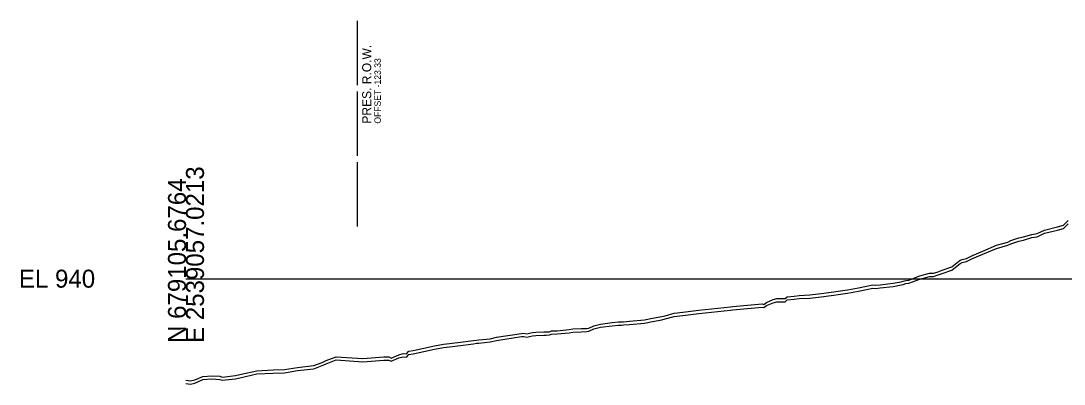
# Model space of a CAD drawing. Extents: x -26 to 2539581, y -16 to 679563.
# Drawn here: x -25.7 to 136.6, y 5483.6 to 5540.1 of the extents above; entities that cross this region are included whole.
import ezdxf

# ---------------------------------------------------------------- set-up
doc = ezdxf.new("R2010")
doc.units = 0
for name, color, linetype in [('DESIGN - SHEET - Light Grid', 7, 'Continuous'), ('SURVEY - GROUND - Bottom of Topsoil Layer', 7, 'Continuous'), ('SURVEY - GROUND - Top of Ground', 7, 'Continuous'), ('SURVEY - PROPERTY - ROW Lines', 7, 'Continuous'), ('SURVEY - PROPERTY - ROW Lines Text', 7, 'Continuous')]:
    doc.layers.add(name, color=color, linetype=linetype)

msp = doc.modelspace()

# ---------------------------------------------------------------- linework, layer by layer
at = {"layer": 'DESIGN - SHEET - Light Grid'}
msp.add_line((0, 5500), (150, 5500), dxfattribs=at)
at = {"layer": 'SURVEY - GROUND - Bottom of Topsoil Layer'}
for p, q in [((136.53, 5507.81), (137.28, 5508.56)), ((131.63, 5506.4), (132.46, 5506.51)), ((132.46, 5506.51), (133.57, 5507.08)), ((133.57, 5507.08), (135.6, 5507.58)), ((135.6, 5507.58), (136.53, 5507.81)), ((126.12, 5504.71), (127.88, 5505.2)), ((127.88, 5505.2), (128.34, 5505.44)), ((128.34, 5505.44), (128.99, 5505.66)), ((128.99, 5505.66), (129.62, 5505.86)), ((129.62, 5505.86), (130.32, 5506.02)), ((130.32, 5506.02), (131.63, 5506.4)), ((122.39, 5503.12), (123.97, 5503.81)), ((123.97, 5503.81), (126.12, 5504.71)), ((119.16, 5501.35), (120.49, 5502.36)), ((120.49, 5502.36), (120.8, 5502.51)), ((120.8, 5502.51), (121.45, 5502.65)), ((121.45, 5502.65), (122.39, 5503.12)), ((114.17, 5499.94), (115.72, 5500.36)), ((115.72, 5500.36), (116.33, 5500.36)), ((116.33, 5500.36), (116.87, 5500.53)), ((116.87, 5500.53), (117.66, 5500.82)), ((117.66, 5500.82), (119.16, 5501.35)), ((105.91, 5498.33), (106.89, 5498.52)), ((106.89, 5498.52), (107.32, 5498.48)), ((107.32, 5498.48), (108, 5498.55)), ((108, 5498.55), (110.05, 5498.8)), ((110.05, 5498.8), (111.29, 5499.03)), ((111.29, 5499.03), (111.6, 5499.1)), ((111.6, 5499.1), (112, 5499.24)), ((112, 5499.24), (112.46, 5499.28)), ((112.46, 5499.28), (114.17, 5499.94)), ((93.55, 5496.69), (94.62, 5496.79)), ((94.62, 5496.79), (95.4, 5496.89)), ((95.4, 5496.89), (97.07, 5496.98)), ((97.07, 5496.98), (99.26, 5497.23)), ((99.26, 5497.23), (99.99, 5497.33)), ((99.99, 5497.33), (100.79, 5497.45)), ((100.79, 5497.45), (101.47, 5497.54)), ((101.47, 5497.54), (102.92, 5497.76)), ((102.92, 5497.76), (104.63, 5498.08)), ((104.63, 5498.08), (105.91, 5498.33)), ((84.74, 5495.1), (85.1, 5495.16)), ((85.1, 5495.16), (89.65, 5495.58)), ((89.65, 5495.58), (89.94, 5495.5)), ((89.94, 5495.5), (90.33, 5495.81)), ((90.33, 5495.81), (91.38, 5496.24)), ((91.38, 5496.24), (91.92, 5496.4)), ((91.92, 5496.4), (93.22, 5496.4)), ((93.22, 5496.4), (93.55, 5496.69)), ((72.58, 5493.35), (74.03, 5493.61)), ((74.03, 5493.61), (74.54, 5493.73)), ((74.54, 5493.73), (75.97, 5494.11)), ((75.97, 5494.11), (77.3, 5494.27)), ((77.3, 5494.27), (79.79, 5494.6)), ((79.79, 5494.6), (84.74, 5495.1)), ((62.71, 5491.82), (63.48, 5492.17)), ((63.48, 5492.17), (64.52, 5492.43)), ((64.52, 5492.43), (66.34, 5492.66)), ((66.34, 5492.66), (67.31, 5492.76)), ((67.31, 5492.76), (67.75, 5492.76)), ((67.75, 5492.76), (68.07, 5492.8)), ((68.07, 5492.8), (68.99, 5492.87)), ((68.99, 5492.87), (71.34, 5493.08)), ((71.34, 5493.08), (72.58, 5493.35)), ((47.35, 5490.16), (48.34, 5490.38)), ((48.34, 5490.38), (52.21, 5490.98)), ((52.21, 5490.98), (52.55, 5491)), ((52.55, 5491), (53.02, 5490.92)), ((53.02, 5490.92), (53.45, 5491)), ((53.45, 5491), (53.93, 5491.12)), ((53.93, 5491.12), (54.43, 5491.16)), ((54.43, 5491.16), (55.69, 5491.2)), ((55.69, 5491.2), (56.05, 5491.22)), ((56.05, 5491.22), (56.54, 5491.25)), ((56.54, 5491.25), (56.88, 5491.37)), ((56.88, 5491.37), (57.76, 5491.4)), ((57.76, 5491.4), (59.62, 5491.59)), ((59.62, 5491.59), (60.19, 5491.67)), ((60.19, 5491.67), (61.49, 5491.73)), ((61.49, 5491.73), (62.39, 5491.76)), ((62.39, 5491.76), (62.71, 5491.82)), ((35.34, 5488.32), (38.69, 5489.04)), ((38.69, 5489.04), (40.07, 5489.3)), ((40.07, 5489.3), (41.01, 5489.39)), ((41.01, 5489.39), (42.73, 5489.62)), ((42.73, 5489.62), (44.33, 5489.8)), ((44.33, 5489.8), (44.73, 5489.86)), ((44.73, 5489.86), (45.2, 5489.94)), ((45.2, 5489.94), (45.55, 5489.97)), ((45.55, 5489.97), (47.35, 5490.16)), ((21.82, 5486.76), (23.39, 5487.35)), ((23.39, 5487.35), (27.54, 5487.07)), ((27.54, 5487.07), (30.77, 5487.31)), ((30.77, 5487.31), (31.57, 5487.32)), ((31.57, 5487.32), (31.93, 5487.15)), ((31.93, 5487.15), (33.13, 5487.66)), ((33.13, 5487.66), (33.8, 5487.85)), ((33.8, 5487.85), (34.33, 5487.8)), ((34.33, 5487.8), (34.67, 5488.22)), ((34.67, 5488.22), (35.34, 5488.32)), ((15.32, 5485.35), (17.34, 5485.68)), ((17.34, 5485.68), (19.91, 5485.96)), ((19.91, 5485.96), (21.2, 5486.47)), ((21.2, 5486.47), (21.82, 5486.76)), ((1.39, 5483.74), (2.6, 5484.28)), ((2.6, 5484.28), (4.03, 5484.39)), ((4.03, 5484.39), (5.28, 5484.3)), ((5.28, 5484.3), (5.64, 5484.19)), ((5.64, 5484.19), (7.68, 5484.43)), ((7.68, 5484.43), (8.38, 5484.58)), ((8.38, 5484.58), (11.04, 5485.16)), ((11.04, 5485.16), (13.59, 5485.31)), ((13.59, 5485.31), (15.32, 5485.35)), ((0, 5483.68), (0.69, 5483.58)), ((0.69, 5483.58), (1.39, 5483.74))]:
    msp.add_line(p, q, dxfattribs=at)
at = {"layer": 'SURVEY - GROUND - Top of Ground'}
msp.add_lwpolyline([(0, 5484.18), (0.69, 5484.08), (1.39, 5484.24), (2.6, 5484.78), (4.03, 5484.89), (5.28, 5484.8), (5.64, 5484.69), (7.68, 5484.93), (8.38, 5485.08), (11.04, 5485.66), (13.59, 5485.81), (15.32, 5485.85), (17.34, 5486.18), (19.91, 5486.46), (21.2, 5486.97), (21.82, 5487.26), (23.39, 5487.85), (27.54, 5487.57), (30.77, 5487.81), (31.57, 5487.82), (31.93, 5487.65), (33.13, 5488.16), (33.8, 5488.35), (34.33, 5488.3), (34.67, 5488.72), (35.34, 5488.82), (38.69, 5489.54), (40.07, 5489.8), (41.01, 5489.89), (42.73, 5490.12), (44.33, 5490.3), (44.73, 5490.36), (45.2, 5490.44), (45.55, 5490.47), (47.35, 5490.66), (48.34, 5490.88), (52.21, 5491.48), (52.55, 5491.5), (53.02, 5491.42), (53.45, 5491.5), (53.93, 5491.62), (54.43, 5491.66), (55.69, 5491.7), (56.05, 5491.72), (56.54, 5491.75), (56.88, 5491.87), (57.76, 5491.9), (59.62, 5492.09), (60.19, 5492.17), (61.49, 5492.23), (62.39, 5492.26), (62.71, 5492.32), (63.48, 5492.67), (64.52, 5492.93), (66.34, 5493.16), (67.31, 5493.26), (67.75, 5493.26), (68.07, 5493.3), (68.99, 5493.37), (71.34, 5493.58), (72.58, 5493.85), (74.03, 5494.11), (74.54, 5494.23), (75.97, 5494.61), (77.3, 5494.77), (79.79, 5495.1), (84.74, 5495.6), (85.1, 5495.66), (89.65, 5496.08), (89.94, 5496), (90.33, 5496.31), (91.38, 5496.74), (91.92, 5496.9), (93.22, 5496.9), (93.55, 5497.19), (94.62, 5497.29), (95.4, 5497.39), (97.07, 5497.48), (99.26, 5497.73), (99.99, 5497.83), (100.79, 5497.95), (101.47, 5498.04), (102.92, 5498.26), (104.63, 5498.58), (105.91, 5498.83), (106.89, 5499.02), (107.32, 5498.98), (108, 5499.05), (110.05, 5499.3), (111.29, 5499.53), (111.6, 5499.6), (112, 5499.74), (112.46, 5499.78), (114.17, 5500.44), (115.72, 5500.86), (116.33, 5500.86), (116.87, 5501.03), (117.66, 5501.32), (119.16, 5501.85), (120.49, 5502.86), (120.8, 5503.01), (121.45, 5503.15), (122.39, 5503.62), (123.97, 5504.31), (126.12, 5505.21), (127.88, 5505.7), (128.34, 5505.94), (128.99, 5506.16), (129.62, 5506.36), (130.32, 5506.52), (131.63, 5506.9), (132.46, 5507.01), (133.57, 5507.58), (135.6, 5508.08), (136.53, 5508.31), (137.28, 5509.06)], dxfattribs=at)
at = {"layer": 'SURVEY - PROPERTY - ROW Lines'}
for p, q in [((26.67, 5530.14), (26.67, 5540.14)), ((26.67, 5519.14), (26.67, 5529.14)), ((26.67, 5508.14), (26.67, 5518.14))]:
    msp.add_line(p, q, dxfattribs=at)

# ---------------------------------------------------------------- texts
at = {"layer": 'DESIGN - SHEET - Light Grid'}
for s, p in [('E 2539057.0213', (2.8, 5490)), ('N 679105.6764', (0, 5490))]:
    msp.add_text(s, height=2.8, rotation=90, dxfattribs=at).set_placement(p)
msp.add_text('EL 940', height=2.8, dxfattribs=at).set_placement((-26, 5498.6))
at = {"layer": 'SURVEY - PROPERTY - ROW Lines Text'}
for s, height, p in [('PRES. R.O.W.', 1.4, (28.82, 5524.14)), ('OFFSET -123.33', 1, (30.32, 5524.14))]:
    msp.add_text(s, height=height, rotation=90, dxfattribs=at).set_placement(p)

doc.saveas('drawing.dxf')
